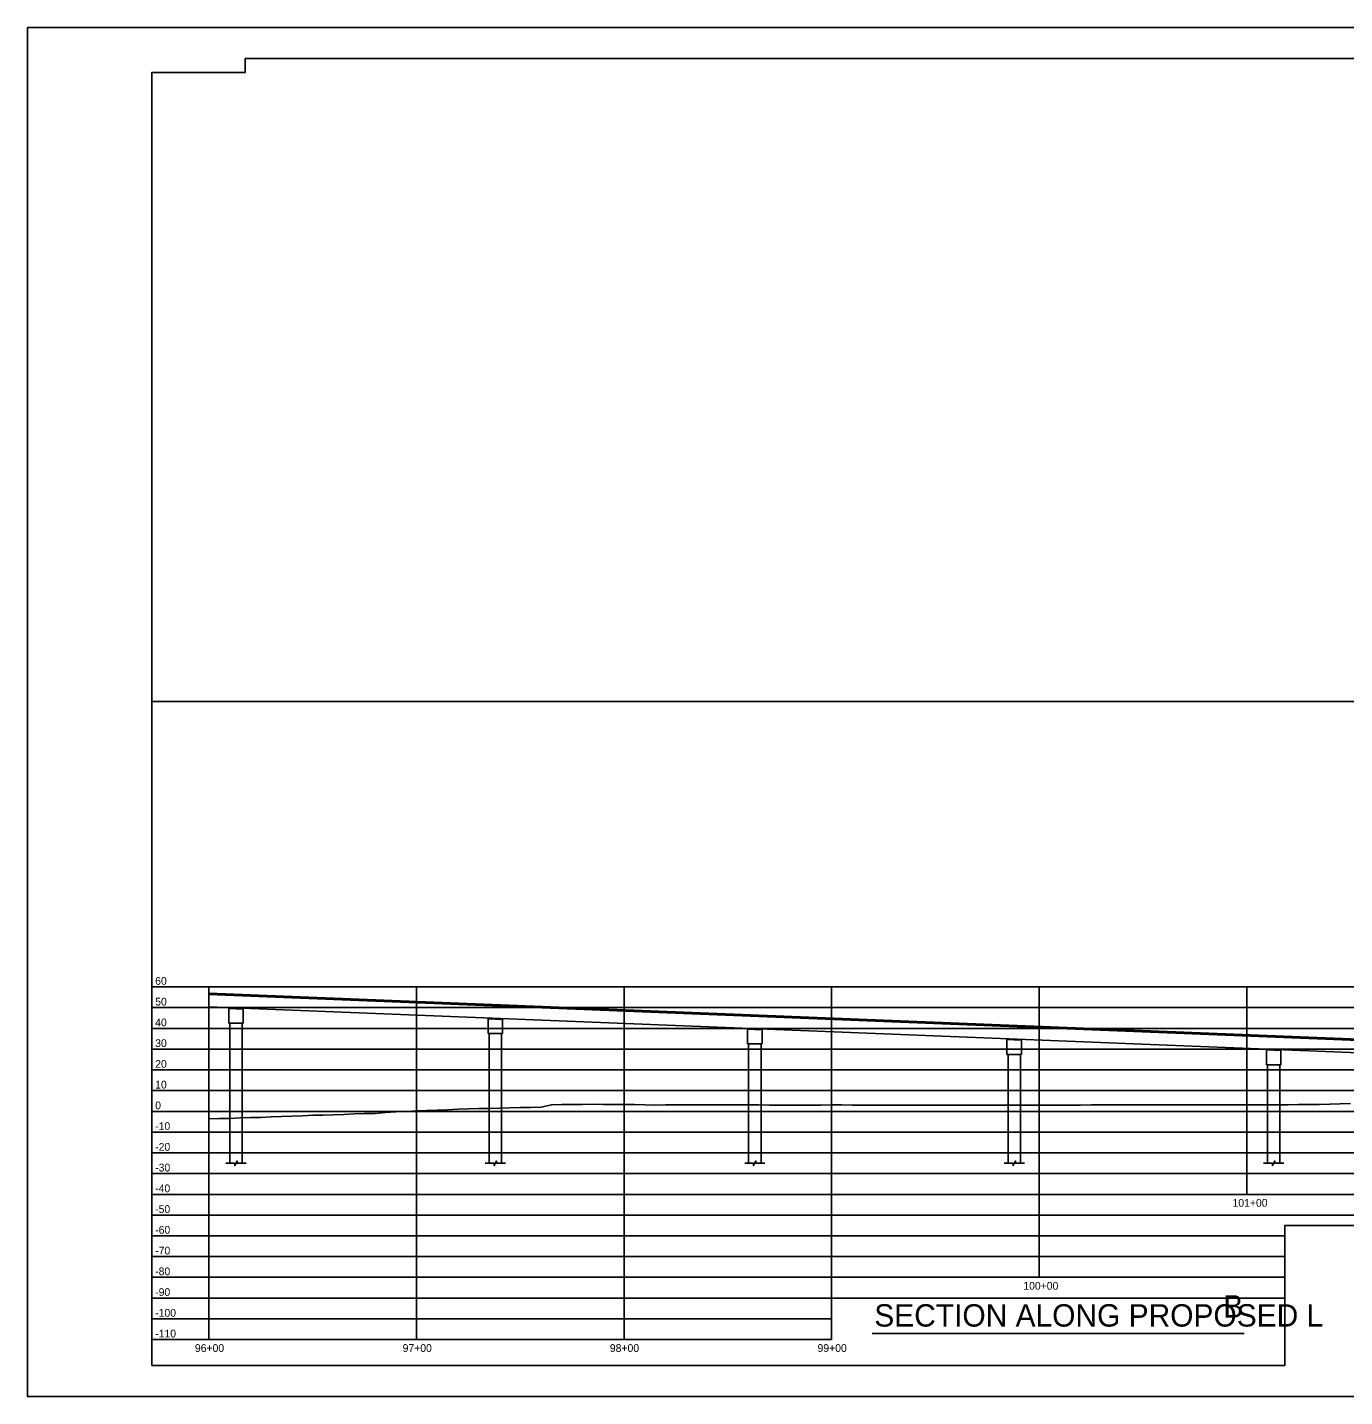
# Model space of a CAD drawing. Extents: x -464 to 4306, y -1372 to 300.
# Drawn here: x 3226 to 3861, y -1372 to -712 of the extents above; entities that cross this region are included whole.
import ezdxf

# ---------------------------------------------------------------- set-up
doc = ezdxf.new("R2010")
doc.units = 0
for name, color, linetype in [('BR_AUTO DIMENSION', 7, 'Continuous'), ('BR_BORDER LINES', 7, 'Continuous'), ('BR_GRID LINES', 7, 'Continuous'), ('BR_TEXT', 7, 'Continuous'), ('Mis Ground Lines', 7, 'Continuous'), ('NOPLOT', 7, 'Continuous'), ('Sheet Plot Border Outside CELL', 7, 'Continuous'), ('sub interior bent cap lines', 7, 'Continuous'), ('Sup Concrete Girder Lines', 7, 'Continuous'), ('Sup Concrete Slab Lines', 7, 'Continuous')]:
    doc.layers.add(name, color=color, linetype=linetype)

msp = doc.modelspace()

# ---------------------------------------------------------------- linework, layer by layer
at = {"layer": 'BR_AUTO DIMENSION'}
msp.add_line((3313.5, -1238.57), (3313.5, -1177.94), dxfattribs=at)
for points in [[(3321.62, -1259.94), (3325.94, -1259.94), (3325.94, -1261.06), (3327.06, -1258.83), (3327.06, -1259.94), (3331.37, -1259.94)], [(3446.62, -1259.94), (3450.94, -1259.94), (3450.94, -1261.06), (3452.06, -1258.83), (3452.06, -1259.94), (3456.37, -1259.94)], [(3571.62, -1259.94), (3575.94, -1259.94), (3575.94, -1261.06), (3577.06, -1258.83), (3577.06, -1259.94), (3581.37, -1259.94)], [(3696.62, -1259.94), (3700.94, -1259.94), (3700.94, -1261.06), (3702.06, -1258.83), (3702.06, -1259.94), (3706.37, -1259.94)], [(3821.62, -1259.94), (3825.94, -1259.94), (3825.94, -1261.06), (3827.06, -1258.83), (3827.06, -1259.94), (3831.37, -1259.94)]]:
    msp.add_lwpolyline(points, dxfattribs=at)
at = {"layer": 'BR_BORDER LINES'}
msp.add_line((3286, -1037.44), (4291, -1037.44), dxfattribs=at)
at = {"layer": 'BR_GRID LINES'}
for p, q in [((3286, -1174.94), (4291, -1174.94)), ((3313.5, -1344.94), (3313.5, -1174.94)), ((3413.5, -1344.94), (3413.5, -1174.94)), ((3513.5, -1344.94), (3513.5, -1174.94)), ((3613.5, -1344.94), (3613.5, -1174.94)), ((3713.5, -1314.94), (3713.5, -1174.94)), ((3813.5, -1274.94), (3813.5, -1174.94)), ((3286, -1184.94), (4291, -1184.94)), ((3286, -1194.94), (4291, -1194.94)), ((3286, -1204.94), (4291, -1204.94)), ((3286, -1214.94), (4291, -1214.94)), ((3286, -1224.94), (4291, -1224.94)), ((3286, -1234.94), (4291, -1234.94)), ((3286, -1244.94), (4291, -1244.94)), ((3286, -1254.94), (4291, -1254.94)), ((3286, -1264.94), (4291, -1264.94)), ((3286, -1274.94), (4066, -1274.94)), ((3286, -1284.94), (4066, -1284.94)), ((3286, -1294.94), (3831.93, -1294.94)), ((3286, -1304.94), (3831.93, -1304.94)), ((3286, -1314.94), (3831.93, -1314.94)), ((3286, -1324.94), (3831.93, -1324.94)), ((3286, -1334.94), (3613.5, -1334.94)), ((3286, -1344.94), (3613.5, -1344.94))]:
    msp.add_line(p, q, dxfattribs=at)
at = {"layer": 'BR_TEXT'}
msp.add_line((3633.09, -1342.1), (3812.35, -1342.1), dxfattribs=at)
at = {"layer": 'Mis Ground Lines'}
for points in [[(3313.5, -1238.57), (3318.5, -1238.44), (3323.5, -1238.33), (3328.5, -1238.12), (3333.5, -1237.98), (3338.5, -1237.84), (3343.5, -1237.54), (3348.5, -1237.39), (3353.5, -1237.24), (3358.5, -1237.06), (3363.5, -1236.86), (3368.5, -1236.75), (3373.5, -1236.58), (3378.5, -1236.4), (3383.5, -1236.2), (3388.5, -1235.97), (3393.5, -1235.94), (3398.5, -1235.56), (3403.5, -1235.24), (3408.5, -1234.97), (3413.5, -1234.75), (3418.5, -1234.55), (3423.5, -1234.35), (3428.5, -1234.15), (3433.5, -1233.96), (3438.5, -1233.76), (3443.5, -1233.62), (3448.5, -1233.5), (3453.5, -1233.38), (3458.5, -1233.26), (3463.5, -1233.14), (3468.5, -1233.03), (3473.5, -1232.91), (3478.5, -1231.76), (3483.5, -1231.66), (3488.5, -1231.7), (3493.5, -1231.71), (3498.5, -1231.53), (3503.5, -1231.63), (3508.5, -1231.67), (3513.5, -1231.57), (3518.5, -1231.7), (3523.5, -1231.84), (3528.5, -1231.9), (3533.5, -1231.86), (3538.5, -1231.82), (3543.5, -1231.86), (3548.5, -1231.87), (3553.5, -1231.81), (3558.5, -1231.86), (3563.5, -1231.83), (3568.5, -1231.78), (3573.5, -1231.81), (3578.5, -1231.83), (3583.5, -1231.88), (3588.5, -1231.9), (3593.5, -1231.93), (3598.5, -1231.91), (3603.5, -1231.89), (3608.5, -1231.95), (3613.5, -1231.85), (3618.5, -1231.85), (3623.5, -1231.88), (3628.5, -1231.94), (3633.5, -1231.97), (3638.5, -1231.98), (3643.5, -1231.97), (3648.5, -1231.93), (3653.5, -1231.9), (3658.5, -1231.91), (3663.5, -1231.94), (3668.5, -1231.91), (3673.5, -1231.94), (3678.5, -1231.95), (3683.5, -1231.94), (3688.5, -1231.93), (3693.5, -1231.89), (3698.5, -1231.92), (3703.5, -1231.95), (3708.5, -1231.91), (3713.5, -1231.88)], [(3713.5, -1231.88), (3718.5, -1231.9), (3723.5, -1231.93), (3728.5, -1231.92), (3733.5, -1231.88), (3738.5, -1231.83), (3743.5, -1231.77), (3748.5, -1231.73), (3753.5, -1231.74), (3758.5, -1231.79), (3763.5, -1231.79), (3768.5, -1231.79), (3773.5, -1231.75), (3778.5, -1231.78), (3783.5, -1231.77), (3788.5, -1231.76), (3793.5, -1231.77), (3798.5, -1231.76), (3803.5, -1231.78), (3808.5, -1231.81), (3813.5, -1231.73), (3818.5, -1231.82), (3823.5, -1231.82), (3828.5, -1231.77), (3833.5, -1231.72), (3838.5, -1231.66), (3843.5, -1231.69), (3848.5, -1231.65), (3853.5, -1231.45), (3858.5, -1231.34), (3863.5, -1231.19)]]:
    msp.add_lwpolyline(points, dxfattribs=at)
at = {"layer": 'NOPLOT'}
msp.add_lwpolyline([(3331, -727.45), (3331, -734.19), (3286, -734.19), (3286, -1357.44), (3831.93, -1357.44), (3831.93, -1289.94), (4066, -1289.94), (4066, -1274.94), (4291, -1274.94), (4291, -747.45), (4216, -747.45), (4216, -727.45)], close=True, dxfattribs=at)
at = {"layer": 'Sheet Plot Border Outside CELL'}
msp.add_lwpolyline([(3226, -712.44), (4306, -712.44), (4306, -1372.44), (3226, -1372.44)], close=True, dxfattribs=at)
at = {"layer": 'sub interior bent cap lines'}
for p, q in [((3323, -1185.33), (3323, -1192.47)), ((3330, -1185.61), (3323, -1185.33)), ((3330, -1185.61), (3330, -1192.47)), ((3323, -1192.47), (3330, -1192.47)), ((3323.5, -1192.47), (3323.5, -1259.94)), ((3329.5, -1192.47), (3329.5, -1259.94)), ((3448, -1190.33), (3448, -1197.47)), ((3455, -1190.61), (3448, -1190.33)), ((3455, -1190.61), (3455, -1197.47)), ((3448, -1197.47), (3455, -1197.47)), ((3448.5, -1197.47), (3448.5, -1259.94)), ((3454.5, -1197.47), (3454.5, -1259.94)), ((3573, -1195.33), (3573, -1202.47)), ((3580, -1195.61), (3573, -1195.33)), ((3580, -1195.61), (3580, -1202.47)), ((3698, -1200.33), (3698, -1207.47)), ((3705, -1200.61), (3698, -1200.33)), ((3705, -1200.61), (3705, -1207.47)), ((3573, -1202.47), (3580, -1202.47)), ((3573.5, -1202.47), (3573.5, -1259.94)), ((3579.5, -1202.47), (3579.5, -1259.94)), ((3698, -1207.47), (3705, -1207.47)), ((3698.5, -1207.47), (3698.5, -1259.94)), ((3704.5, -1207.47), (3704.5, -1259.94)), ((3823, -1205.33), (3823, -1212.47)), ((3823, -1205.33), (3830, -1205.61)), ((3830, -1205.61), (3830, -1212.47)), ((3823, -1212.47), (3830, -1212.47)), ((3823.5, -1212.47), (3823.5, -1259.94)), ((3829.5, -1212.47), (3829.5, -1259.94))]:
    msp.add_line(p, q, dxfattribs=at)
at = {"layer": 'Sup Concrete Girder Lines'}
for p, q in [((3313.5, -1178.61), (4068.47, -1208.81)), ((3313.5, -1184.62), (4068.23, -1214.81))]:
    msp.add_line(p, q, dxfattribs=at)
at = {"layer": 'Sup Concrete Slab Lines'}
msp.add_line((3313.5, -1177.94), (4068.5, -1208.14), dxfattribs=at)

# ---------------------------------------------------------------- texts
at = {"layer": 'BR_TEXT'}
for s, p in [('60', (3287.58, -1173.94)), ('50', (3287.58, -1183.94)), ('40', (3287.58, -1193.94)), ('30', (3287.58, -1203.94)), ('20', (3287.58, -1213.94)), ('10', (3287.58, -1223.94)), ('0', (3287.58, -1233.94)), ('-10', (3287.58, -1243.94)), ('-20', (3287.58, -1253.94)), ('-30', (3287.58, -1263.94)), ('-40', (3287.58, -1273.94)), ('-50', (3287.58, -1283.94)), ('101+00', (3806.69, -1280.91)), ('-60', (3287.58, -1293.94)), ('-70', (3287.58, -1303.94)), ('-80', (3287.58, -1313.94)), ('100+00', (3705.87, -1320.91)), ('-90', (3287.58, -1323.94)), ('-100', (3287.58, -1333.94)), ('-110', (3287.58, -1343.94)), ('96+00', (3306.72, -1350.91)), ('97+00', (3406.81, -1350.91)), ('98+00', (3506.66, -1350.91)), ('99+00', (3606.72, -1350.91))]:
    msp.add_text(s, height=3.75, rotation=360, dxfattribs=at).set_placement(p)
for s, height, p in [('B', 10.78, (3802.24, -1334.33)), ('SECTION ALONG PROPOSED L', 10.7809, (3634.07, -1338.69))]:
    msp.add_text(s, height=height, dxfattribs=at).set_placement(p)

doc.saveas('drawing.dxf')
